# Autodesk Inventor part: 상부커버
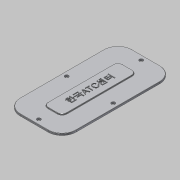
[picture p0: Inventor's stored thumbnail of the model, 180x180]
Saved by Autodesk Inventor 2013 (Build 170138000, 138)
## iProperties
Created: 2016-02
Part Number: 상부커버
Material: 알루미늄 6061
Document SubType Name: Modeling
Designer: mduedu
Density: 1 g/cm^3
Mass: 15.5198 g
Surface Area: 149.263 cm^2
Volume: 15.5198 cm^3
Author: mduedu
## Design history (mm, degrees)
sketch "스케치1"
  geometry: L1 (30, 60)-(-30, 60); L2 (-30, 60)-(-30, -60); L3 (-30, -60)-(30, -60); L4 (30, -60)-(30, 60); L5 (30, 60)-(-30, -60); L6 (-30, 60)-(30, -60); 1 further point
  constraints: 12 end point, 2 midpoint, 2 parallel, 1 horizontal, 1 perpendicular
  dimensions: "d0" = 60 distance of L2.end L3.end; "d2" = 120 distance of L1.end L2.end
extrude "돌출1" new body sketch "스케치1" distance "d3" = 2; taper "d4" = 0 deg
fillet "모깎기1" dims "d5" = 15
sketch "스케치2"
  geometry: L1 (30, 45)-(30, -45) reference; L2 (15, -60)-(-15, -60) reference; L3 (-30, -45)-(-30, 45) reference; L4 (-15, 60)-(15, 60) reference; L5 (25, 45)-(25, -45); L6 (15, -55)-(-15, -55); L7 (-25, -45)-(-25, 45); L8 (-15, 55)-(15, 55); A1 r 15 centre (15, 45) between (30, 45) and (15, 60) reference; A2 r 15 centre (15, -45) between (15, -60) and (30, -45) reference; A3 r 15 centre (-15, -45) between (-30, -45) and (-15, -60) reference; A4 r 15 centre (-15, 45) between (-15, 60) and (-30, 45) reference; A5 r 10 centre (15, 45) between (25, 45) and (15, 55); A6 r 10 centre (15, -45) between (15, -55) and (25, -45); A7 r 10 centre (-15, -45) between (-25, -45) and (-15, -55); A8 r 10 centre (-15, 45) between (-15, 55) and (-25, 45); 4 further points
  constraints: 8 end point, 8 point on circle, 4 centre point, 4 midpoint, 7 other
  dimensions: "d8" = 5 distance between parallel lines of L7 L3
hole "구멍1" sketch "스케치2" at (0, 55), (25, 0), (0, -55), (-25, 0) diameter "d9" = 4; stored, may be unused: countersink angle "d13" = 90 deg, drill point angle "d15" = 118 deg; dims "d10" = 6, "d11" = 4, "d12" = 2, "d14" = 8
sketch "스케치3"
  geometry: L1 (10, -40)-(-10, -40); L2 (-10, -40)-(-10, 40); L3 (-10, 40)-(10, 40); L4 (10, 40)-(10, -40); L5 (10, -40)-(-10, 40); L6 (-10, -40)-(10, 40); 1 further point
  constraints: 12 end point, 2 midpoint, 2 parallel, 1 horizontal, 1 perpendicular
  dimensions: "d16" = 80 distance of L1.end L2.end; "d18" = 20 distance of L2.end L3.end
extrude "돌출2" join sketch "스케치3" distance "d19" = 1; taper "d20" = 0 deg
fillet "모깎기2" dims "d21" = 5
fillet "모깎기3" dims "d22" = 0.3
fillet "모깎기4" dims "d23" = 0.3
sketch "스케치4"
  geometry: 2 further points
  constraints: 1 coincident, 1 other
feature "엠보싱1" sketch "스케치4" dims "d0" = 60, "d2" = 120, "d8" = 5, "d24" = 0.5, "d25" = 0
node "솔리드1"
node "절단 모서리 투영1"
